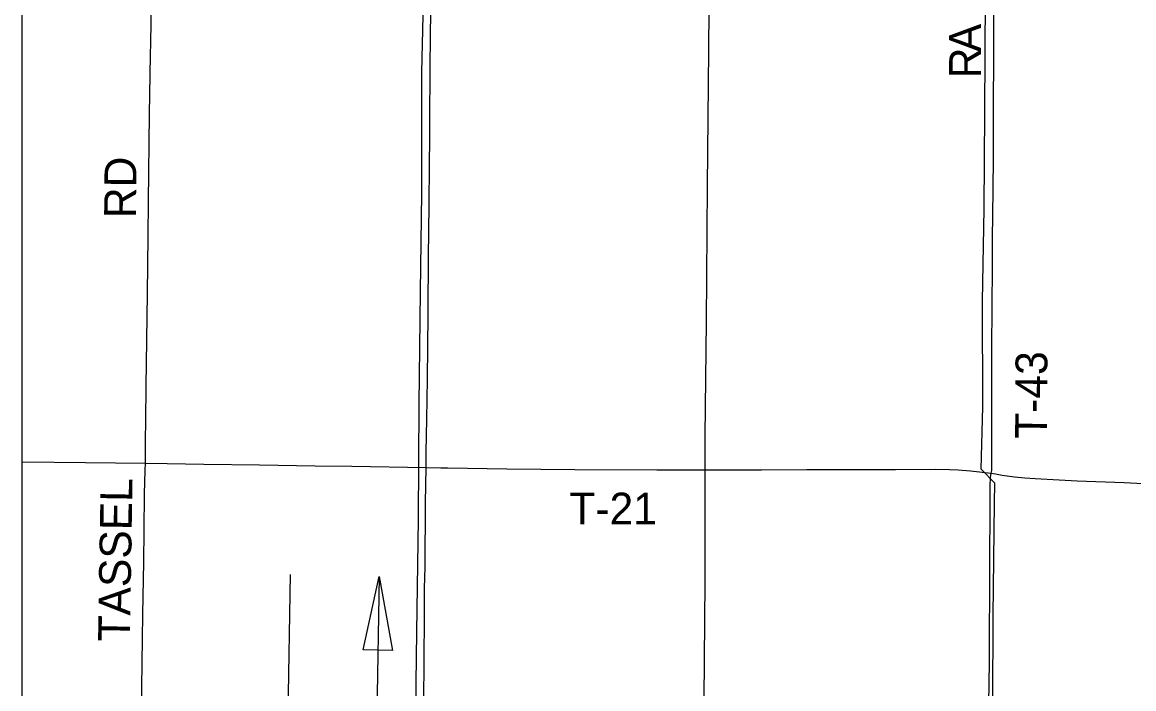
# Model space of a CAD drawing. Extents: x 0 to 680, y 0 to 834.
# Drawn here: x 44.7 to 120.8, y 223.2 to 268.9 of the extents above; entities that cross this region are included whole.
import ezdxf

# ---------------------------------------------------------------- set-up
doc = ezdxf.new("R2010")
doc.units = 0
for name, color, linetype in [('GM_X_Interstate_Route', 7, 'Continuous'), ('GM_X_Minor_River', 7, 'Continuous'), ('GM_X_State_Route', 7, 'Continuous'), ('GM_X_Township_Road', 7, 'Continuous'), ('GM_X_Township_Road_Text', 7, 'Continuous'), ('SH_Text', 7, 'Continuous')]:
    doc.layers.add(name, color=color, linetype=linetype)

msp = doc.modelspace()

# ---------------------------------------------------------------- linework, layer by layer
at = {"layer": 'GM_X_Interstate_Route'}
msp.add_lwpolyline([(44.693, 394.069), (374.693, 394.069), (374.693, 64.069), (44.693, 64.069)], close=True, dxfattribs=at)
at = {"layer": 'GM_X_Minor_River'}
for points in [[(92.297, 320.37), (92.2, 311.072), (92.094, 303.817), (91.987, 294.711), (91.894, 283.026), (91.784, 275.495), (91.7, 266.958), (91.604, 257.679), (91.536, 248.37), (91.449, 240.548), (91.442, 230.554), (91.365, 219.848), (91.291, 211.968), (91.2, 203.054), (91.208, 197.474), (91.042, 190.192), (90.977, 182.865), (90.897, 176.367), (90.732, 166.476)], [(111.183, 222.254), (111.21, 228.212), (111.295, 235.947), (111.318, 237.316), (110.388, 238.264), (110.488, 242.545), (110.478, 249.772), (110.583, 256.108), (110.635, 262.723), (110.681, 270.736), (110.754, 276.024), (110.793, 280.118), (110.751, 284.592), (110.946, 292.764), (110.98, 299.204), (111.059, 304.828), (111.126, 310.626), (111.186, 315.099), (111.243, 319.426)], [(72.531, 312.418), (72.49, 306.389), (72.401, 300.139), (72.391, 291.63), (72.269, 282.599), (72.232, 277.748), (72.217, 273.29), (72.043, 265.454), (72.036, 257.165), (71.953, 250.45), (71.867, 242.716), (71.808, 234.821), (71.709, 227.13), (71.59, 218.304)]]:
    msp.add_lwpolyline(points, dxfattribs=at)
at = {"layer": 'GM_X_State_Route'}
for points in [[(72.655, 267.088), (72.656, 267.124), (72.668, 267.858), (72.699, 271.538), (72.748, 276.287), (72.759, 277.117)], [(72.197, 222.484), (72.227, 224.99), (72.256, 228.332), (72.261, 230.123), (72.285, 231.555), (72.327, 235.971), (72.361, 238.39), (72.375, 239.432), (72.408, 241.701), (72.46, 244.445), (72.503, 248.861), (72.532, 253.04), (72.552, 254.352), (72.604, 261.156), (72.648, 266.647), (72.655, 267.088)]]:
    msp.add_lwpolyline(points, dxfattribs=at)
at = {"layer": 'GM_X_Township_Road'}
for points in [[(53.495, 267.504), (53.541, 270.204), (53.561, 271.868), (53.599, 274.959), (53.594, 276.513), (53.58, 276.989), (53.573, 277.274), (53.568, 277.442)], [(111.072, 237.987), (111.111, 238.177), (111.117, 238.296), (111.107, 238.763), (111.108, 240.076), (111.104, 241.031), (111.122, 245.925), (111.14, 249.984), (111.153, 251.535), (111.156, 254.043), (111.204, 257.385), (111.222, 259.653), (111.231, 261.204), (111.23, 262.398), (111.239, 263.711), (111.24, 265.979), (111.24, 267.77), (111.249, 270.277), (111.249, 272.425), (111.244, 273.738), (111.239, 275.051), (111.241, 276.006), (111.251, 276.944), (111.252, 276.982)], [(53.134, 238.679), (53.134, 238.946), (53.139, 240.259), (53.167, 241.572), (53.189, 243.96), (53.264, 250.288), (53.314, 254.227), (53.34, 256.615), (53.421, 262.585), (53.48, 266.644), (53.495, 267.504)], [(44.693, 238.765), (44.719, 238.765), (49.016, 238.729), (53.134, 238.679)], [(52.906, 199.994), (52.902, 200.366), (52.892, 201.442), (52.927, 205.864), (52.969, 210.525), (53.013, 214.229), (53.046, 215.424), (53.04, 216.5), (53.029, 218.053), (53.005, 218.65), (52.937, 219.724), (52.898, 220.798), (52.882, 221.993), (52.891, 223.308), (52.932, 226.654), (52.958, 228.327), (53.017, 231.912), (53.045, 234.063), (53.074, 236.573), (53.116, 238.171), (53.134, 238.679)], [(53.134, 238.679), (54.626, 238.661), (57.133, 238.624), (60.952, 238.572), (64.771, 238.508), (67.278, 238.475), (72.361, 238.39)], [(72.361, 238.39), (73.365, 238.373), (73.843, 238.358), (77.9, 238.293), (82.556, 238.248), (88.166, 238.224), (93.06, 238.221), (95.328, 238.236), (98.432, 238.244), (100.461, 238.237), (102.013, 238.242), (104.519, 238.25), (107.265, 238.264), (108.221, 238.25), (108.818, 238.224), (109.652, 238.148), (111.072, 237.987)], [(110.766, 199.519), (110.777, 200.467), (110.813, 205.48), (110.847, 212.642), (110.869, 214.791), (110.876, 216.462), (110.891, 219.447), (110.903, 222.192), (110.953, 225.057), (110.956, 226.25), (110.978, 230.548), (110.982, 232.816), (110.992, 234.726), (111, 237.114), (111.023, 237.709), (111.039, 237.827), (111.072, 237.987)], [(111.072, 237.987), (111.361, 237.943), (111.831, 237.87), (112.66, 237.756), (113.373, 237.678), (114.089, 237.623), (116.951, 237.482), (120.172, 237.36), (121.483, 237.296), (122.915, 237.237), (124.822, 237.139), (128.281, 236.978), (130.19, 236.915), (131.86, 236.848), (133.768, 236.757), (136.034, 236.661), (139.015, 236.514), (140.923, 236.425), (146.409, 236.165), (148.197, 236.071), (149.454, 236.017)]]:
    msp.add_lwpolyline(points, dxfattribs=at)
at = {"layer": 'SH_Text'}
for p, q in [((62.603, 205.43), (63.079, 231.052)), ((69.151, 230.915), (68.675, 205.294))]:
    msp.add_line(p, q, dxfattribs=at)
msp.add_lwpolyline([(68.05, 225.895), (69.151, 230.915), (70.065, 225.857)], close=True, dxfattribs=at)

# ---------------------------------------------------------------- texts
at = {"layer": 'GM_X_Township_Road_Text'}
for s, height, rotation, p in [('A', 2.182, 90, (110.371, 266.844)), ('R', 2.182, 90, (110.371, 265.052)), ('RD', 2.1818, 89.50633, (52.483, 255.46)), ('T-43', 2.1818, 89.64631, (114.888, 240.345)), ('TASSEL', 2.1818, 89.06595, (52.067, 226.451)), ('T-21', 2.1818, 0.00001, (82.173, 234.481))]:
    msp.add_text(s, height=height, rotation=rotation, dxfattribs=at).set_placement(p)

doc.saveas('drawing.dxf')
